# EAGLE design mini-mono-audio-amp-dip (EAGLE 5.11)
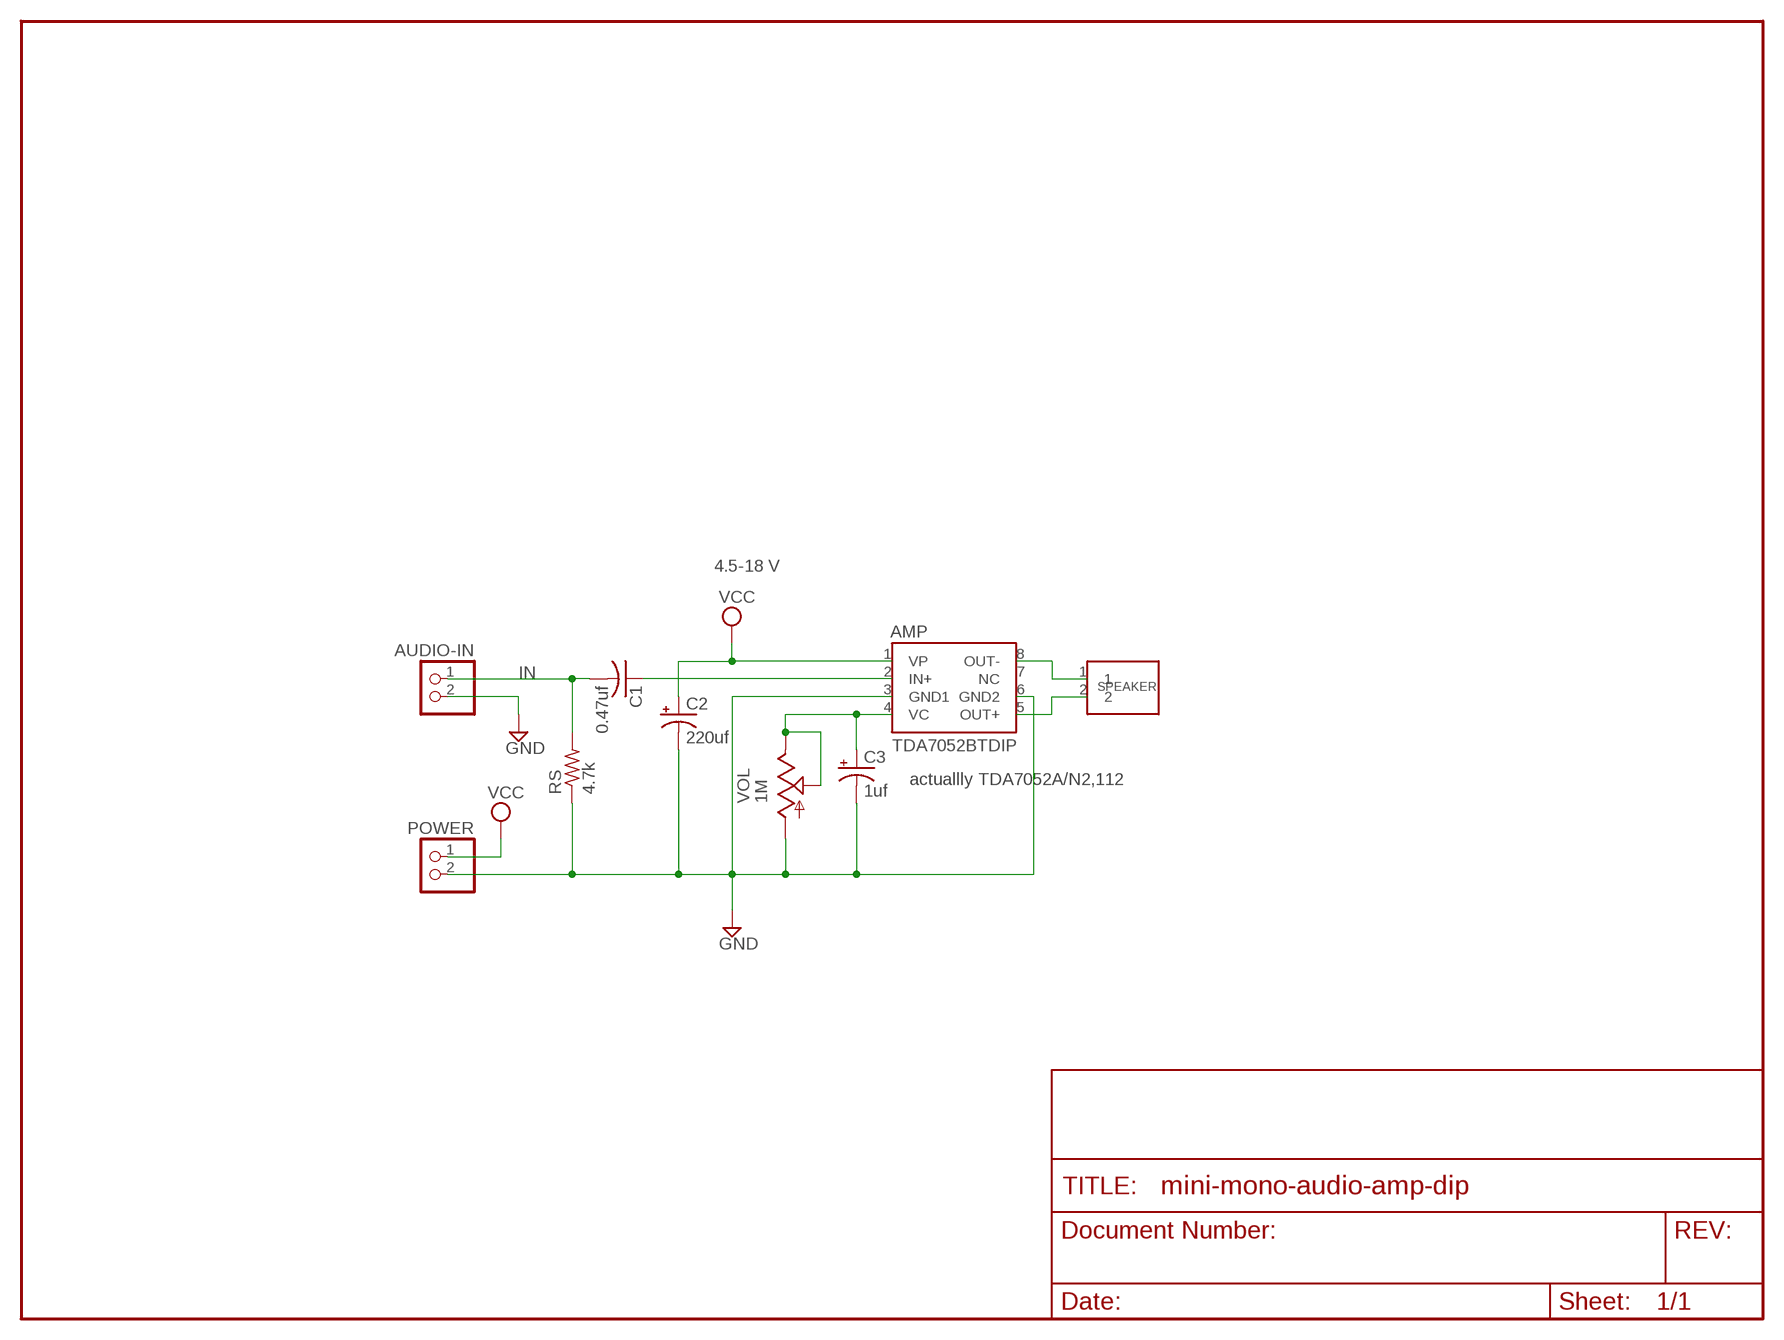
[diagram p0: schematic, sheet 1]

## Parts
AMP  TDA7052BTDIP  [8DIP]
AUDIO-IN  PINHD-1X2  [1X02]
C1  0.47uf  C-US025-025X050  [C025-025X050]
C2  220uf  CPOL-USE5-10.5  [E5-10,5]
C3  1uf  CPOL-USE2-5  [E2-5]
POWER  PINHD-1X2  [1X02]
RS  4.7k  R-US_0207/12  [0207/12]
SPEAKER  HEADER2-PUSHIN  [HEADER2-PUSHIN]
VOL  1M  POT-TRIM-3.5IN  [POT-TRIM-3.5IN]

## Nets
GND: AMP.3(GND1) AMP.6(GND2) AUDIO-IN.2 C2.- C3.- POWER.2 RS.1 VOL.1(A)
IN: AUDIO-IN.1 C1.2 RS.2
N$1: AMP.2(IN+) C1.1
N$3: AMP.4(VC) C3.+ VOL.2(S) VOL.3(E)
N$4: AMP.5(OUT+) SPEAKER.2
N$5: AMP.8(OUT-) SPEAKER.1
VCC: AMP.1(VP) C2.+ POWER.1
Unconnected: AMP.7(NC)

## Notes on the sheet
- 4.5-18 V
- actuallly TDA7052A/N2,112

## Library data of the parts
AMP = trl:TDA7052BT
AUDIO-IN POWER = pinhead:PINHD-1X2: PIN HEADER
C1 = rcl:C-US: CAPACITOR, American symbol
C2 C3 = resistor:CPOL-US: POLARIZED CAPACITOR, American symbol
RS = rcl:R-US_: RESISTOR, American symbol
SPEAKER = trl:HEADER2-PUSHIN
VOL = trl:POT-TRIM-3.5IN

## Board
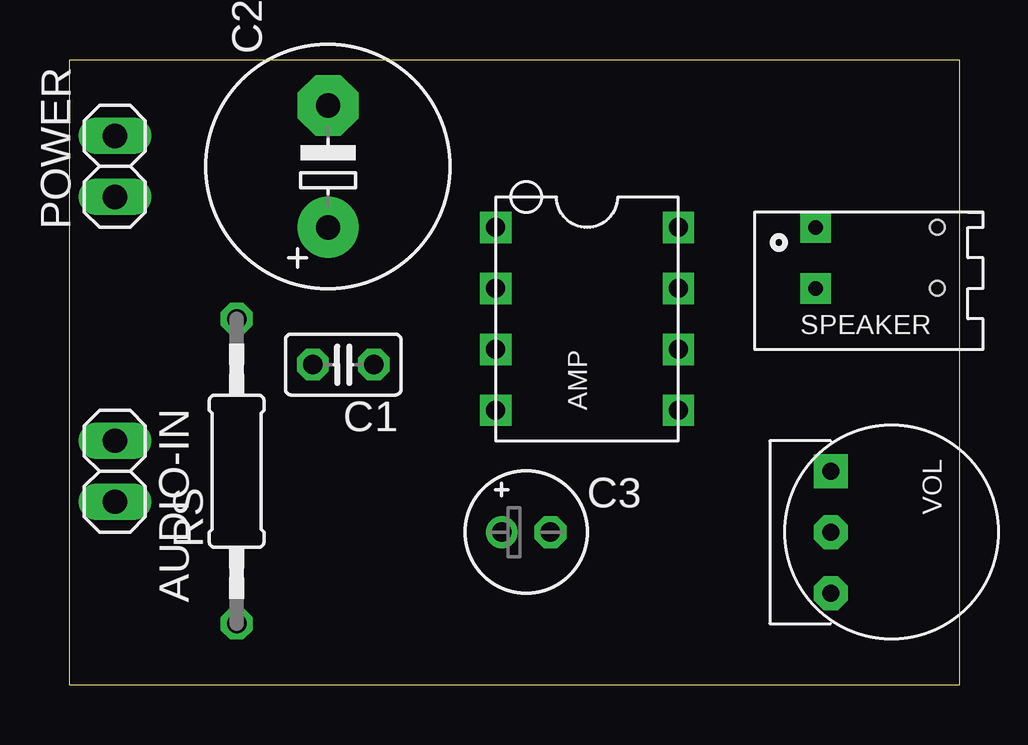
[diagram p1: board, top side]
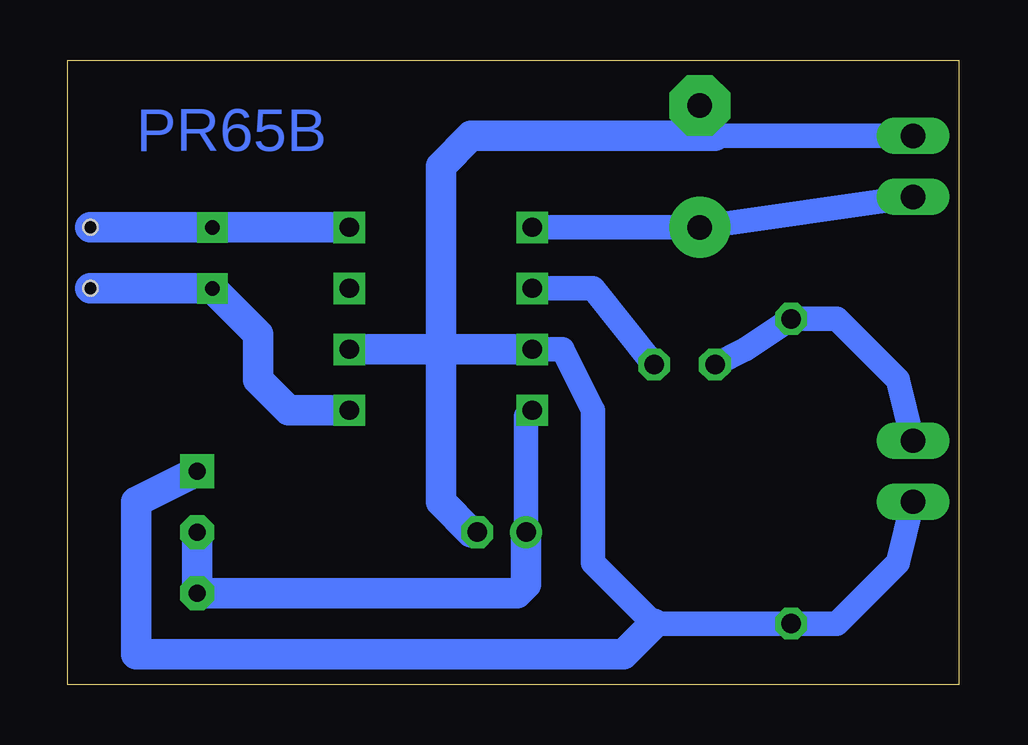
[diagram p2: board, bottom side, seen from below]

Size 37.13 x 26.02 mm. Coordinates in mm from the lower left corner, seen from the top.
Outline: 0,0 37.13,0 37.13,26.02 0,26.02 0,0
Copper layers (1*16): Top 0.035mm / dielectric 1.5mm / Bottom 0.035mm
Design rules "default": minimum track width 10mil, minimum drill 24mil, track to track 8mil, track to pad 8mil, pad to pad 8mil, via to via 8mil, smd to smd 8mil, copper to edge 40mil, drill to drill 8mil, minimum pad ring 10mil, minimum via ring 8mil, stop-mask expansion 4mil, vias tented up to drill 0mil, thermal gap 10mil

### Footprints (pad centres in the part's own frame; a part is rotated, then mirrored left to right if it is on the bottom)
8DIP = drill 0.8 square: 1 -3.81,3.81; 2 -3.81,1.27; 3 -3.81,-1.27; 4 -3.81,-3.81; 5 3.81,-3.81; 6 3.81,-1.27; 7 3.81,1.27; 8 3.81,3.81
1X02 = drill 1.016 long: 1 -1.27,0; 2 1.27,0
C025-025X050 = drill 0.813 octagon: 1 -1.27,0; 2 1.27,0
E5-10,5 = drill 1.016 pad 2.54 round: + -2.54,0 | drill 1.016 pad 2.54 octagon: - 2.54,0
E2-5 = drill 0.813 pad 1.27 round: + -1.016,0 | drill 0.813 pad 1.27 octagon: - 1.016,0
0207/12 = drill 0.813 octagon: 1 -6.35,0; 2 6.35,0
HEADER2-PUSHIN = drill 0.6 pad 1.27 square: 1 -1.905,1.27; 2 -1.905,-1.27 | hole 0.6: 3.175,1.27; 3.175,-1.27
POT-TRIM-3.5IN = drill 0.7 pad 1.422 square: 1 -2.54,-3.81 | drill 0.7 pad 1.422 octagon: 2 0,-3.81; 3 2.54,-3.81

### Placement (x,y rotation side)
AMP  21.59,15.24 0 top
AUDIO-IN  1.91,8.89 270 top
C1  11.43,13.34 180 top
C2  10.79,21.59 90 top
C3  19.05,6.35 0 top
POWER  1.91,21.59 90 top
RS  6.99,8.89 90 top
SPEAKER  33.02,17.78 0 top
VOL  35.56,6.35 270 top

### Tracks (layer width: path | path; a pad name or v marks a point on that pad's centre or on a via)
GND
  Bottom 1.016: POWER.2 10.16,22.86 C2.- | AMP.3 16.51,13.97 15.24,11.43 15.24,5.08 12.7,2.54 RS.1 5.08,2.54 2.54,5.08 AUDIO-IN.2
  Bottom 1.27: VOL.1 34.29,7.62 34.29,6.35 34.29,1.27 29.21,1.27 13.97,1.27 12.7,2.54 | AMP.3 21.59,13.97 | 21.59,13.97 AMP.6 | 10.16,22.86 20.32,22.86 21.59,21.59 21.59,13.97 | C3.- 20.32,6.35 21.59,7.62 21.59,13.97
IN
  Bottom 1.016: C1.2 8.89,13.97 RS.2 5.08,15.24 2.54,12.7 AUDIO-IN.1
N$1
  Bottom 1.016: AMP.2 15.24,16.51 C1.1
N$3
  Bottom 1.016: C3.+ 18.03,11.18 AMP.4
  Bottom 1.27: C3.+ 18.03,4.19 18.41,3.81 26.67,3.81 VOL.3 VOL.2
N$4
  Bottom 1.27: AMP.5 27.94,11.43 29.21,12.7 29.21,14.61 SPEAKER.2
N$5
  Bottom 1.27: AMP.8 SPEAKER.1
VCC
  Bottom 1.016: POWER.1 C2.+ AMP.1

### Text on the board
Bottom: PR65B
